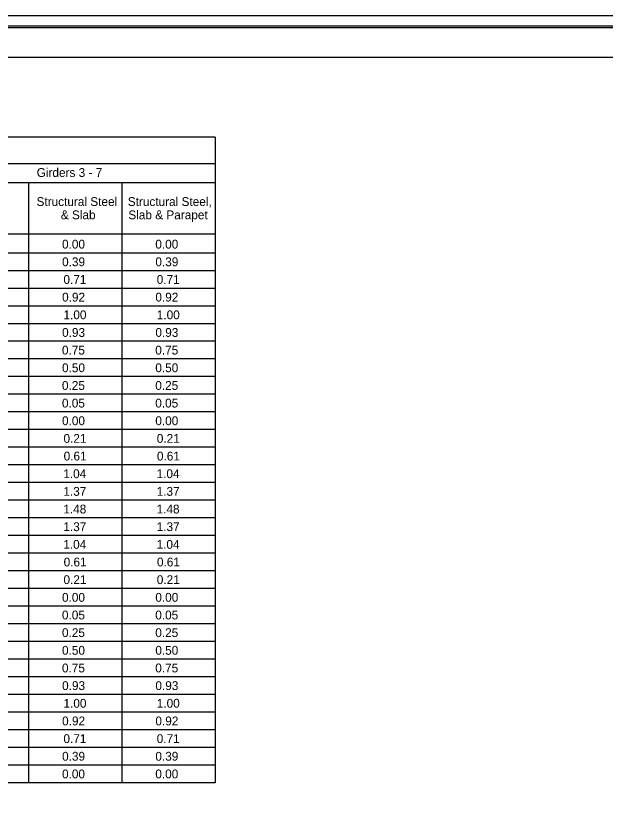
# Model space of a CAD drawing. Extents: x -725.7 to -683.7, y 85.6 to 107.6.
# Drawn here: x -712.63 to -704.28, y 96.51 to 107.6 of the extents above; entities that cross this region are included whole.
import ezdxf

# ---------------------------------------------------------------- set-up
doc = ezdxf.new("R2010")
doc.units = 0
for name, color, linetype in [('border', 7, 'Continuous'), ('Border 2660-Hwy18 - Level 62', 7, 'Continuous'), ('Border 2660-Hwy18 - Level 63', 7, 'Continuous'), ('Level 62 PDF', 7, 'Continuous'), ('Steel', 7, 'Continuous'), ('Text', 7, 'Continuous')]:
    doc.layers.add(name, color=color, linetype=linetype)

msp = doc.modelspace()

# ---------------------------------------------------------------- linework, layer by layer
at = {"layer": 'border'}
msp.add_line((-723.942, 107.01), (-691.93, 107.01), dxfattribs=at)
at = {"layer": 'Border 2660-Hwy18 - Level 62'}
msp.add_lwpolyline([(-725.562, 107.596), (-691.443, 107.596), (-691.443, 85.786), (-725.562, 85.786)], close=True, dxfattribs=at)
at = {"layer": 'Border 2660-Hwy18 - Level 63'}
msp.add_lwpolyline([(-725.673, 107.453), (-691.673, 107.453), (-691.673, 86.083), (-725.673, 86.083)], close=True, dxfattribs=at)
at = {"layer": 'Level 62 PDF'}
msp.add_lwpolyline([(-725.312, 107.429), (-691.193, 107.429), (-691.193, 85.62), (-725.312, 85.62)], close=True, dxfattribs=at)
at = {"layer": 'Steel'}
for p, q in [((-709.806, 105.876), (-723.289, 105.876)), ((-709.806, 105.876), (-709.806, 96.735)), ((-709.806, 105.499), (-723.289, 105.499)), ((-709.806, 105.23), (-721.704, 105.23)), ((-712.45, 105.23), (-712.45, 96.735)), ((-711.128, 105.23), (-711.128, 96.735)), ((-709.806, 104.503), (-723.289, 104.503)), ((-709.806, 104.235), (-722.496, 104.235)), ((-709.806, 103.985), (-722.496, 103.985)), ((-709.806, 103.735), (-722.496, 103.735)), ((-709.806, 103.485), (-722.496, 103.485)), ((-709.806, 103.235), (-722.496, 103.235)), ((-709.806, 102.985), (-722.496, 102.985)), ((-709.806, 102.735), (-722.496, 102.735)), ((-709.806, 102.485), (-722.496, 102.485)), ((-709.806, 102.235), (-722.496, 102.235)), ((-709.806, 101.985), (-722.496, 101.985)), ((-709.806, 101.735), (-722.496, 101.735)), ((-709.806, 101.485), (-722.496, 101.485)), ((-709.806, 101.235), (-722.496, 101.235)), ((-709.806, 100.985), (-722.496, 100.985)), ((-709.806, 100.735), (-722.496, 100.735)), ((-709.806, 100.485), (-722.496, 100.485)), ((-709.806, 100.235), (-722.496, 100.235)), ((-709.806, 99.985), (-722.496, 99.985)), ((-709.806, 99.735), (-722.496, 99.735)), ((-709.806, 99.485), (-722.496, 99.485)), ((-709.806, 99.235), (-722.496, 99.235)), ((-709.806, 98.985), (-722.496, 98.985)), ((-709.806, 98.735), (-722.496, 98.735)), ((-709.806, 98.485), (-722.496, 98.485)), ((-709.806, 98.235), (-722.496, 98.235)), ((-709.806, 97.985), (-722.496, 97.985)), ((-709.806, 97.735), (-722.496, 97.735)), ((-709.806, 97.485), (-722.496, 97.485)), ((-709.806, 97.235), (-722.496, 97.235)), ((-709.806, 96.985), (-722.496, 96.985)), ((-709.806, 96.735), (-723.289, 96.735))]:
    msp.add_line(p, q, dxfattribs=at)

# ---------------------------------------------------------------- texts
at = {"layer": 'Text'}
for s, p in [('Girders 3 - 7', (-712.334, 105.312)), ('Structural Steel', (-712.336, 104.901)), ('Structural Steel,', (-711.043, 104.901)), ('& Slab', (-711.992, 104.713)), ('Slab & Parapet', (-711.035, 104.713)), ('0.00', (-711.975, 104.298)), ('0.00', (-710.653, 104.298)), ('0.39', (-711.974, 104.048)), ('0.39', (-710.652, 104.048)), ('0.71', (-711.955, 103.798)), ('0.71', (-710.633, 103.798)), ('0.92', (-711.974, 103.548)), ('0.92', (-710.652, 103.548)), ('1.00', (-711.954, 103.298)), ('1.00', (-710.632, 103.298)), ('0.93', (-711.974, 103.048)), ('0.93', (-710.652, 103.048)), ('0.75', (-711.976, 102.798)), ('0.75', (-710.654, 102.798)), ('0.50', (-711.975, 102.548)), ('0.50', (-710.653, 102.548)), ('0.25', (-711.976, 102.298)), ('0.25', (-710.654, 102.298)), ('0.05', (-711.976, 102.048)), ('0.05', (-710.654, 102.048)), ('0.00', (-711.975, 101.798)), ('0.00', (-710.653, 101.798)), ('0.21', (-711.954, 101.548)), ('0.21', (-710.632, 101.548)), ('0.61', (-711.952, 101.298)), ('0.61', (-710.63, 101.298)), ('1.04', (-711.957, 101.048)), ('1.04', (-710.635, 101.048)), ('1.37', (-711.956, 100.798)), ('1.37', (-710.634, 100.798)), ('1.48', (-711.957, 100.548)), ('1.48', (-710.635, 100.548)), ('1.37', (-711.956, 100.298)), ('1.37', (-710.634, 100.298)), ('1.04', (-711.957, 100.048)), ('1.04', (-710.635, 100.048)), ('0.61', (-711.952, 99.798)), ('0.61', (-710.63, 99.798)), ('0.21', (-711.954, 99.548)), ('0.21', (-710.632, 99.548)), ('0.00', (-711.975, 99.298)), ('0.00', (-710.653, 99.298)), ('0.05', (-711.976, 99.048)), ('0.05', (-710.654, 99.048)), ('0.25', (-711.976, 98.798)), ('0.25', (-710.654, 98.798)), ('0.50', (-711.975, 98.548)), ('0.50', (-710.653, 98.548)), ('0.75', (-711.976, 98.298)), ('0.75', (-710.654, 98.298)), ('0.93', (-711.974, 98.048)), ('0.93', (-710.652, 98.048)), ('1.00', (-711.954, 97.798)), ('1.00', (-710.632, 97.798)), ('0.92', (-711.974, 97.548)), ('0.92', (-710.652, 97.548)), ('0.71', (-711.955, 97.298)), ('0.71', (-710.633, 97.298)), ('0.39', (-711.974, 97.048)), ('0.39', (-710.652, 97.048)), ('0.00', (-711.975, 96.798)), ('0.00', (-710.653, 96.798))]:
    msp.add_text(s, height=0.125, dxfattribs=at).set_placement(p)

doc.saveas('drawing.dxf')
